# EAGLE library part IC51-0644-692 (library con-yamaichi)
Series IC51 (Clamshell) Bumper Quad Flat Packages (BQFP) 64 contacts Source: http://www.yamaichi.de/pdfqfp/IC51-0644-692.pdf
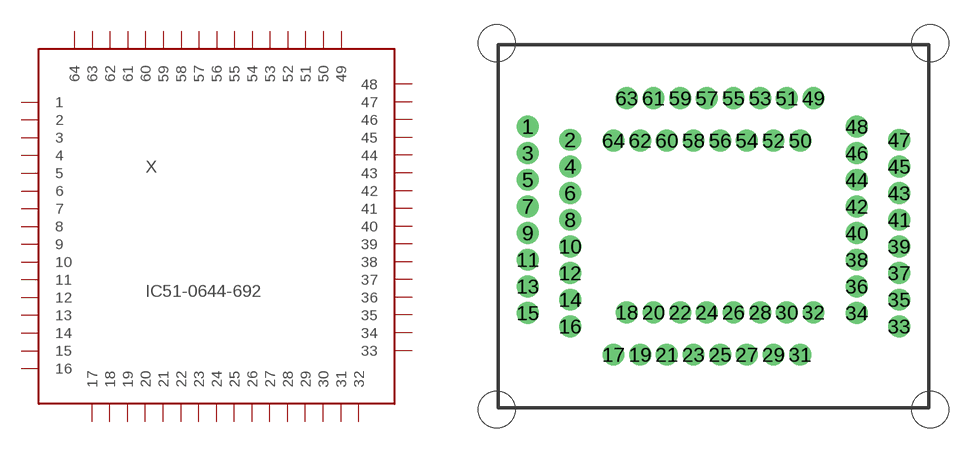
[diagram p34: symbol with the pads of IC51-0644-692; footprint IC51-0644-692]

Designator prefix X

## IC51-0644-692 (OC_FARNELL: unknown; OC_NEWARK: unknown)  [IC51-0644-692]
1  1  pas
2  2  pas
3  3  pas
4  4  pas
5  5  pas
6  6  pas
7  7  pas
8  8  pas
9  9  pas
10  10  pas
11  11  pas
12  12  pas
13  13  pas
14  14  pas
15  15  pas
16  16  pas
17  17  pas
18  18  pas
19  19  pas
20  20  pas
21  21  pas
22  22  pas
23  23  pas
24  24  pas
25  25  pas
26  26  pas
27  27  pas
28  28  pas
29  29  pas
30  30  pas
31  31  pas
32  32  pas
33  33  pas
34  34  pas
35  35  pas
36  36  pas
37  37  pas
38  38  pas
39  39  pas
40  40  pas
41  41  pas
42  42  pas
43  43  pas
44  44  pas
45  45  pas
46  46  pas
47  47  pas
48  48  pas
49  49  pas
50  50  pas
51  51  pas
52  52  pas
53  53  pas
54  54  pas
55  55  pas
56  56  pas
57  57  pas
58  58  pas
59  59  pas
60  60  pas
61  61  pas
62  62  pas
63  63  pas
64  64  pas

## Footprint IC51-0644-692 (pad centres in mm)
Series IC51 (Clamshell) Bumper Quad Flat Packages (BQFP) 64 contacts Source: http://www.yamaichi.de/pdfqfp/IC51-0644-692.pdf
drill 0.8 pad 1.27 round: 1 -11.14,6; 2 -8.6,5.2; 3 -11.14,4.4; 4 -8.6,3.6; 5 -11.14,2.8; 6 -8.6,2; 7 -11.14,1.2; 8 -8.6,0.4; 9 -11.14,-0.4; 10 -8.6,-1.2; 11 -11.14,-2; 12 -8.6,-2.8; 13 -11.14,-3.6; 14 -8.6,-4.4; 15 -11.14,-5.2; 16 -8.6,-6; 17 -6,-7.7; 18 -5.2,-5.16; 19 -4.4,-7.7; 20 -3.6,-5.16; 21 -2.8,-7.7; 22 -2,-5.16; 23 -1.2,-7.7; 24 -0.4,-5.16; 25 0.4,-7.7; 26 1.2,-5.16; 27 2,-7.7; 28 2.8,-5.16; 29 3.6,-7.7; 30 4.4,-5.16; 31 5.2,-7.7; 32 6,-5.16; 33 11.14,-6; 34 8.6,-5.2; 35 11.14,-4.4; 36 8.6,-3.6; 37 11.14,-2.8; 38 8.6,-2; 39 11.14,-1.2; 40 8.6,-0.4; 41 11.14,0.4; 42 8.6,1.2; 43 11.14,2; 44 8.6,2.8; 45 11.14,3.6; 46 8.6,4.4; 47 11.14,5.2; 48 8.6,6; 49 6,7.7; 50 5.2,5.16; 51 4.4,7.7; 52 3.6,5.16; 53 2.8,7.7; 54 2,5.16; 55 1.2,7.7; 56 0.4,5.16; 57 -0.4,7.7; 58 -1.2,5.16; 59 -2,7.7; 60 -2.8,5.16; 61 -3.6,7.7; 62 -4.4,5.16; 63 -5.2,7.7; 64 -6,5.16
hole 2.2 at -13,11
hole 2.2 at 13,11
hole 2.2 at -13,-11
hole 2.2 at 13,-11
